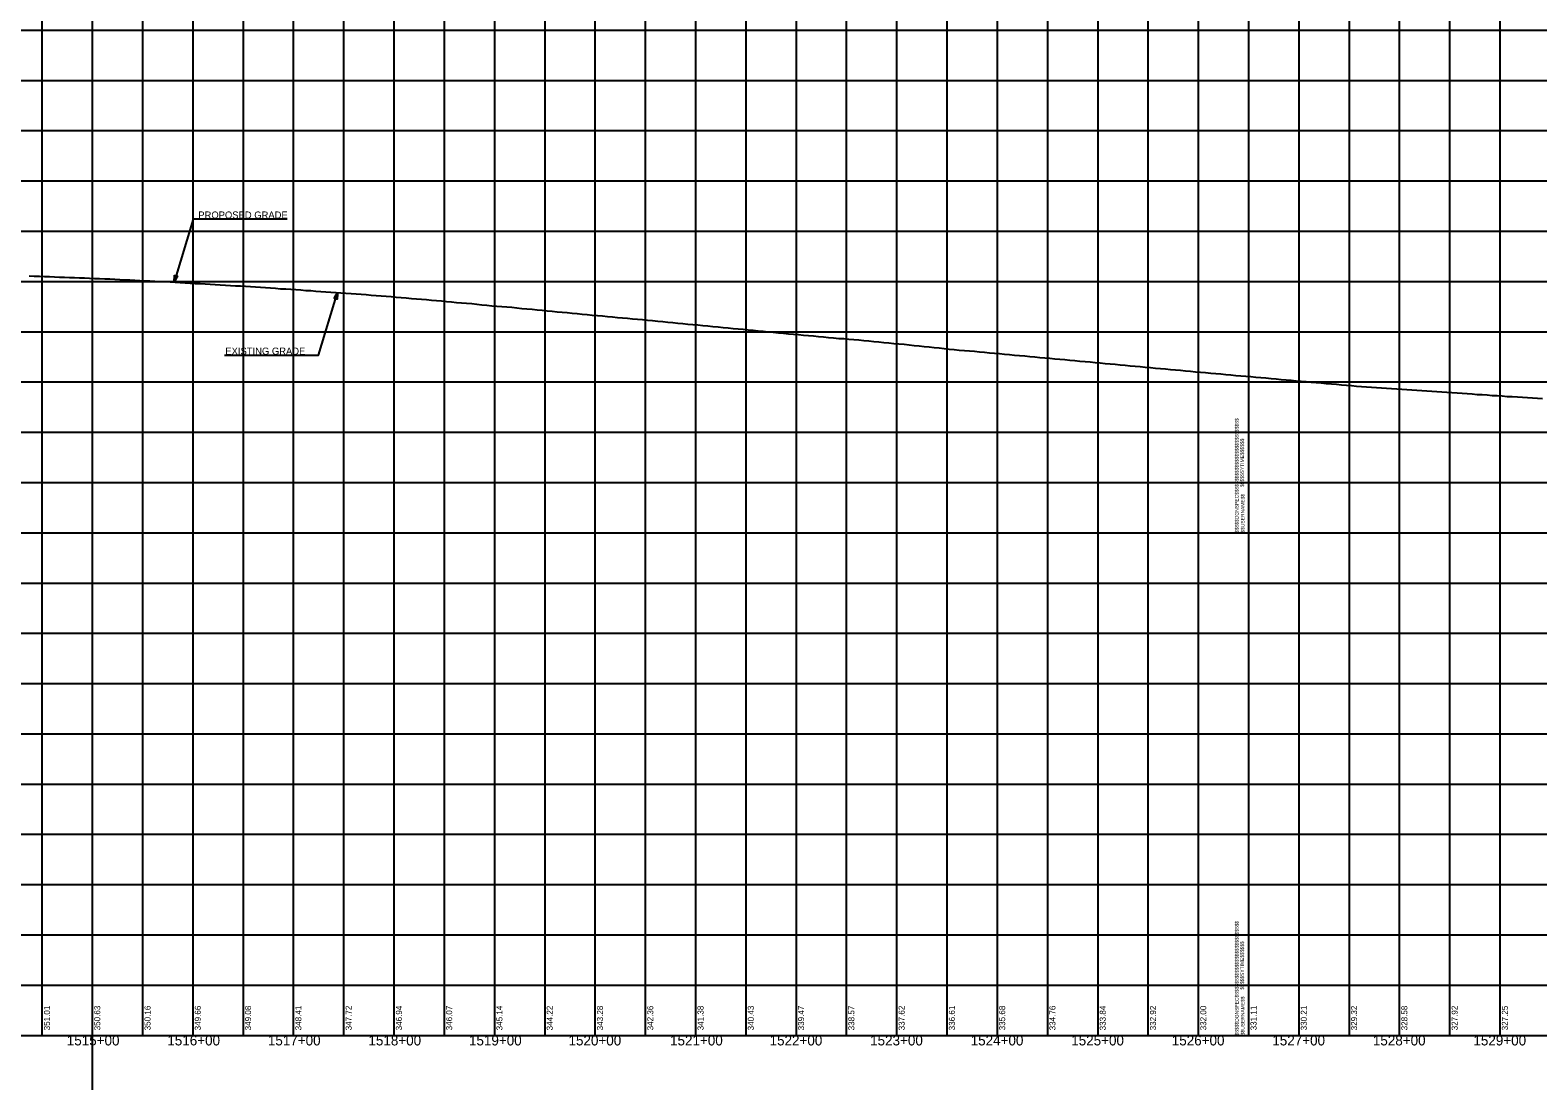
# Model space of a CAD drawing. Extents: x -90830 to 2015517, y -20856 to 836331.
# Drawn here: x 40362 to 41861, y -19432 to -18387 of the extents above; entities that cross this region are included whole.
import ezdxf

# ---------------------------------------------------------------- set-up
doc = ezdxf.new("R2010")
doc.units = 0
for name, color, linetype in [('Level 1', 7, 'Continuous'), ('RD_DDB_Profile_EX', 7, 'Continuous'), ('RD_DDB_StaTX', 7, 'Continuous'), ('RD_DDB_StripGrade', 7, 'Continuous'), ('RD_GPK_Profile_Cell', 7, 'Continuous'), ('RD_PD_Final_TX', 7, 'Continuous')]:
    doc.layers.add(name, color=color, linetype=linetype)

msp = doc.modelspace()

# ---------------------------------------------------------------- linework, layer by layer
at = {"layer": 'Level 1'}
for p, q in [((40423.5, -12693.4), (40423.5, -20856.1)), ((40373.5, -17886.5), (40373.5, -18386.5)), ((40423.5, -17886.5), (40423.5, -18386.5)), ((40473.5, -17886.5), (40473.5, -18386.5)), ((40523.5, -17886.5), (40523.5, -18386.5)), ((40573.5, -17886.5), (40573.5, -18386.5)), ((40623.5, -17886.5), (40623.5, -18386.5)), ((40673.5, -17886.5), (40673.5, -18386.5)), ((40723.5, -17886.5), (40723.5, -18386.5)), ((40773.5, -17886.5), (40773.5, -18386.5)), ((40823.5, -17886.5), (40823.5, -18386.5)), ((40873.5, -17886.5), (40873.5, -18386.5)), ((40923.5, -17886.5), (40923.5, -18386.5)), ((40973.5, -17886.5), (40973.5, -18386.5)), ((41023.5, -17886.5), (41023.5, -18386.5)), ((41073.5, -17886.5), (41073.5, -18386.5)), ((41123.5, -17886.5), (41123.5, -18386.5)), ((41173.5, -17886.5), (41173.5, -18386.5)), ((41223.5, -17886.5), (41223.5, -18386.5)), ((41273.5, -17886.5), (41273.5, -18386.5)), ((41323.5, -17886.5), (41323.5, -18386.5)), ((41373.5, -17886.5), (41373.5, -18386.5)), ((41423.5, -17886.5), (41423.5, -18386.5)), ((41473.5, -17886.5), (41473.5, -18386.5)), ((41523.5, -17886.5), (41523.5, -18386.5)), ((41573.5, -17886.5), (41573.5, -18386.5)), ((41573.5, -17886.5), (41573.5, -18386.5)), ((41573.5, -17886.5), (41573.5, -18386.5)), ((41623.5, -17886.5), (41623.5, -18386.5)), ((41673.5, -17886.5), (41673.5, -18386.5)), ((41723.5, -17886.5), (41723.5, -18386.5)), ((41773.5, -17886.5), (41773.5, -18386.5)), ((41823.5, -17886.5), (41823.5, -18386.5)), ((39973.5, -18386.5), (41573.5, -18386.5)), ((39973.5, -18386.5), (41573.5, -18386.5)), ((40373.5, -18386.5), (40373.5, -18886.5)), ((40423.5, -18386.5), (40423.5, -18886.5)), ((40473.5, -18386.5), (40473.5, -18886.5)), ((40523.5, -18386.5), (40523.5, -18886.5)), ((40573.5, -18386.5), (40573.5, -18886.5)), ((40623.5, -18386.5), (40623.5, -18886.5)), ((40673.5, -18386.5), (40673.5, -18886.5)), ((40723.5, -18386.5), (40723.5, -18886.5)), ((40773.5, -18386.5), (40773.5, -18886.5)), ((40823.5, -18386.5), (40823.5, -18886.5)), ((40873.5, -18386.5), (40873.5, -18886.5)), ((40923.5, -18386.5), (40923.5, -18886.5)), ((40973.5, -18386.5), (40973.5, -18886.5)), ((41023.5, -18386.5), (41023.5, -18886.5)), ((41073.5, -18386.5), (41073.5, -18886.5)), ((41123.5, -18386.5), (41123.5, -18886.5)), ((41173.5, -18386.5), (41173.5, -18886.5)), ((41223.5, -18386.5), (41223.5, -18886.5)), ((41273.5, -18386.5), (41273.5, -18886.5)), ((41323.5, -18386.5), (41323.5, -18886.5)), ((41373.5, -18386.5), (41373.5, -18886.5)), ((41423.5, -18386.5), (41423.5, -18886.5)), ((41473.5, -18386.5), (41473.5, -18886.5)), ((41523.5, -18386.5), (41523.5, -18886.5)), ((41573.5, -18386.5), (41573.5, -18886.5)), ((41573.5, -18386.5), (41573.5, -18886.5)), ((41573.5, -18386.5), (43173.5, -18386.5)), ((41573.5, -18386.5), (41573.5, -18886.5)), ((41573.5, -18386.5), (43173.5, -18386.5)), ((41623.5, -18386.5), (41623.5, -18886.5)), ((41673.5, -18386.5), (41673.5, -18886.5)), ((41723.5, -18386.5), (41723.5, -18886.5)), ((41773.5, -18386.5), (41773.5, -18886.5)), ((41823.5, -18386.5), (41823.5, -18886.5)), ((39973.5, -18436.5), (41573.5, -18436.5)), ((41573.5, -18436.5), (43173.5, -18436.5)), ((39973.5, -18486.5), (41573.5, -18486.5)), ((41573.5, -18486.5), (43173.5, -18486.5)), ((39973.5, -18536.5), (41573.5, -18536.5)), ((41573.5, -18536.5), (43173.5, -18536.5)), ((39973.5, -18586.5), (41573.5, -18586.5)), ((41573.5, -18586.5), (43173.5, -18586.5)), ((39973.5, -18636.5), (41573.5, -18636.5)), ((41573.5, -18636.5), (43173.5, -18636.5)), ((39973.5, -18686.5), (41573.5, -18686.5)), ((41573.5, -18686.5), (43173.5, -18686.5)), ((39973.5, -18736.5), (41573.5, -18736.5)), ((41573.5, -18736.5), (43173.5, -18736.5)), ((39973.5, -18786.5), (41573.5, -18786.5)), ((41573.5, -18786.5), (43173.5, -18786.5)), ((39973.5, -18836.5), (41573.5, -18836.5)), ((41573.5, -18836.5), (43173.5, -18836.5)), ((39973.5, -18886.5), (41573.5, -18886.5)), ((39973.5, -18886.5), (41573.5, -18886.5)), ((40373.5, -18886.5), (40373.5, -19386.5)), ((40423.5, -18886.5), (40423.5, -19386.5)), ((40473.5, -18886.5), (40473.5, -19386.5)), ((40523.5, -18886.5), (40523.5, -19386.5)), ((40573.5, -18886.5), (40573.5, -19386.5)), ((40623.5, -18886.5), (40623.5, -19386.5)), ((40673.5, -18886.5), (40673.5, -19386.5)), ((40723.5, -18886.5), (40723.5, -19386.5)), ((40773.5, -18886.5), (40773.5, -19386.5)), ((40823.5, -18886.5), (40823.5, -19386.5)), ((40873.5, -18886.5), (40873.5, -19386.5)), ((40923.5, -18886.5), (40923.5, -19386.5)), ((40973.5, -18886.5), (40973.5, -19386.5)), ((41023.5, -18886.5), (41023.5, -19386.5)), ((41073.5, -18886.5), (41073.5, -19386.5)), ((41123.5, -18886.5), (41123.5, -19386.5)), ((41173.5, -18886.5), (41173.5, -19386.5)), ((41223.5, -18886.5), (41223.5, -19386.5)), ((41273.5, -18886.5), (41273.5, -19386.5)), ((41323.5, -18886.5), (41323.5, -19386.5)), ((41373.5, -18886.5), (41373.5, -19386.5)), ((41423.5, -18886.5), (41423.5, -19386.5)), ((41473.5, -18886.5), (41473.5, -19386.5)), ((41523.5, -18886.5), (41523.5, -19386.5)), ((41573.5, -18886.5), (43173.5, -18886.5)), ((41573.5, -18886.5), (41573.5, -19386.5)), ((41573.5, -18886.5), (41573.5, -19386.5)), ((41573.5, -18886.5), (43173.5, -18886.5)), ((41573.5, -18886.5), (41573.5, -19386.5)), ((41623.5, -18886.5), (41623.5, -19386.5)), ((41673.5, -18886.5), (41673.5, -19386.5)), ((41723.5, -18886.5), (41723.5, -19386.5)), ((41773.5, -18886.5), (41773.5, -19386.5)), ((41823.5, -18886.5), (41823.5, -19386.5)), ((39973.5, -18936.5), (41573.5, -18936.5)), ((41573.5, -18936.5), (43173.5, -18936.5)), ((39973.5, -18986.5), (41573.5, -18986.5)), ((41573.5, -18986.5), (43173.5, -18986.5)), ((39973.5, -19036.5), (41573.5, -19036.5)), ((41573.5, -19036.5), (43173.5, -19036.5)), ((39973.5, -19086.5), (41573.5, -19086.5)), ((41573.5, -19086.5), (43173.5, -19086.5)), ((39973.5, -19136.5), (41573.5, -19136.5)), ((41573.5, -19136.5), (43173.5, -19136.5)), ((39973.5, -19186.5), (41573.5, -19186.5)), ((41573.5, -19186.5), (43173.5, -19186.5)), ((39973.5, -19236.5), (41573.5, -19236.5)), ((41573.5, -19236.5), (43173.5, -19236.5)), ((39973.5, -19286.5), (41573.5, -19286.5)), ((41573.5, -19286.5), (43173.5, -19286.5)), ((39973.5, -19336.5), (41573.5, -19336.5)), ((41573.5, -19336.5), (43173.5, -19336.5)), ((39973.5, -19386.5), (41573.5, -19386.5)), ((41573.5, -19386.5), (43173.5, -19386.5))]:
    msp.add_line(p, q, dxfattribs=at)
at = {"layer": 'RD_DDB_Profile_EX'}
for points in [[(40360.9, -18630.9), (40365.9, -18631.2), (40370.9, -18631.4), (40375.9, -18631.6), (40380.9, -18631.7), (40385.9, -18631.9), (40390.9, -18632.1), (40395.9, -18632.3), (40400.9, -18632.5), (40405.9, -18632.6), (40410.9, -18632.9), (40415.9, -18633), (40420.9, -18633.3)], [(40420.9, -18633.3), (40425.9, -18633.5), (40430.9, -18633.6), (40435.9, -18633.8), (40440.9, -18634), (40445.9, -18634.3), (40450.9, -18634.6), (40455.9, -18634.8), (40460.9, -18635), (40465.9, -18635.3), (40470.9, -18635.6), (40475.9, -18635.8), (40480.9, -18636), (40485.9, -18636.2), (40490.9, -18636.5), (40495.9, -18636.7), (40500.9, -18636.9), (40505.9, -18637.2), (40510.9, -18637.6), (40515.9, -18637.8), (40520.9, -18638.1), (40525.9, -18638.4), (40530.9, -18638.7), (40535.9, -18638.9), (40540.9, -18639.2), (40545.9, -18639.6), (40550.9, -18639.9), (40555.9, -18640.1), (40560.9, -18640.4), (40565.9, -18640.7), (40570.9, -18641), (40575.9, -18641.2), (40580.9, -18641.6), (40585.9, -18642), (40590.9, -18642.3), (40595.9, -18642.5), (40600.9, -18643), (40605.9, -18643.3), (40610.9, -18643.7), (40615.9, -18644), (40620.9, -18644.3), (40625.9, -18644.6), (40630.9, -18645), (40635.9, -18645.4), (40640.9, -18645.6), (40645.9, -18646), (40650.9, -18646.4), (40655.9, -18646.7), (40660.9, -18647), (40665.9, -18647.4), (40670.9, -18647.8), (40675.9, -18648.1), (40680.9, -18648.4), (40685.9, -18648.8), (40690.9, -18649.2), (40695.9, -18649.6), (40700.9, -18650), (40705.9, -18650.4), (40710.9, -18650.9), (40715.9, -18651.3), (40720.9, -18651.6), (40725.9, -18652.1), (40730.9, -18652.5), (40735.9, -18652.9), (40740.9, -18653.4), (40745.9, -18653.8), (40750.9, -18654.2), (40755.9, -18654.6), (40760.9, -18655), (40765.9, -18655.5), (40770.9, -18655.9), (40775.9, -18656.4), (40780.9, -18656.9), (40785.9, -18657.3), (40790.9, -18657.8), (40795.9, -18658.2), (40800.9, -18658.6), (40805.9, -18659.1), (40810.9, -18659.7), (40815.9, -18660.1), (40820.9, -18660.6), (40825.9, -18661), (40830.9, -18661.5), (40835.9, -18661.9), (40840.9, -18662.2), (40845.9, -18662.8), (40850.9, -18663.3), (40855.9, -18663.8), (40860.9, -18664.2), (40865.9, -18664.7), (40870.9, -18665.2), (40875.9, -18665.6), (40880.9, -18666.1), (40885.9, -18666.6), (40890.9, -18667), (40895.9, -18667.5), (40900.9, -18668), (40905.9, -18668.4), (40910.9, -18668.9), (40915.9, -18669.4), (40920.9, -18669.9)], [(40920.9, -18669.9), (40925.9, -18670.4), (40930.9, -18670.8), (40935.9, -18671.3), (40940.9, -18671.8), (40945.9, -18672.2), (40950.9, -18672.6), (40955.9, -18673.1), (40960.9, -18673.6), (40965.9, -18674), (40970.9, -18674.5), (40975.9, -18674.9), (40980.9, -18675.4), (40985.9, -18675.9), (40990.9, -18676.3), (40995.9, -18676.9), (41000.9, -18677.4), (41005.9, -18678), (41010.9, -18678.4), (41015.9, -18678.9), (41020.9, -18679.4), (41025.9, -18679.8), (41030.9, -18680.3), (41035.9, -18680.7), (41040.9, -18681.3), (41045.9, -18681.7), (41050.9, -18682.2), (41055.9, -18682.7), (41060.9, -18683.2), (41065.9, -18683.7), (41070.9, -18684.1), (41075.9, -18684.6), (41080.9, -18685.1), (41085.9, -18685.6), (41090.9, -18686.1), (41095.9, -18686.5), (41100.9, -18687), (41105.9, -18687.5), (41110.9, -18687.9), (41115.9, -18688.5), (41120.9, -18688.9), (41125.9, -18689.3), (41130.9, -18689.8), (41135.9, -18690.2), (41140.9, -18690.7), (41145.9, -18691.1), (41150.9, -18691.6), (41155.9, -18692.1), (41160.9, -18692.5), (41165.9, -18693.1), (41170.9, -18693.4), (41175.9, -18693.9), (41180.9, -18694.4), (41185.9, -18694.7), (41190.9, -18695.2), (41195.9, -18695.7), (41200.9, -18696.1), (41205.9, -18696.7), (41210.9, -18697.1), (41215.9, -18697.6), (41220.9, -18698.1), (41225.9, -18698.6), (41230.9, -18699), (41235.9, -18699.5), (41240.9, -18700.1), (41245.9, -18700.6), (41250.9, -18701.1), (41255.9, -18701.6), (41260.9, -18702.1), (41265.9, -18702.7), (41270.9, -18703.2), (41275.9, -18703.7), (41280.9, -18704.2), (41285.9, -18704.7), (41290.9, -18705.1), (41295.9, -18705.6), (41300.9, -18706), (41305.9, -18706.5), (41310.9, -18707), (41315.9, -18707.4), (41320.9, -18707.9), (41325.9, -18708.3), (41330.9, -18708.8), (41335.9, -18709.3), (41340.9, -18709.7), (41345.9, -18710.2), (41350.9, -18710.6), (41355.9, -18711.1), (41360.9, -18711.6), (41365.9, -18712), (41370.9, -18712.5), (41375.9, -18712.9), (41380.9, -18713.4), (41385.9, -18713.9), (41390.9, -18714.3), (41395.9, -18714.8), (41400.9, -18715.2), (41405.9, -18715.7), (41410.9, -18716.2), (41415.9, -18716.6), (41420.9, -18717.1)], [(41420.9, -18717.1), (41425.9, -18717.5), (41430.9, -18718), (41435.9, -18718.5), (41440.9, -18718.9), (41445.9, -18719.4), (41450.9, -18719.8), (41455.9, -18720.3), (41460.9, -18720.8), (41465.9, -18721.2), (41470.9, -18721.7), (41475.9, -18722.2), (41480.9, -18722.6), (41485.9, -18723.1), (41490.9, -18723.5), (41495.9, -18724), (41500.9, -18724.5), (41505.9, -18724.9), (41510.9, -18725.4), (41515.9, -18725.8), (41520.9, -18726.3), (41525.9, -18726.7), (41530.9, -18727.2), (41535.9, -18727.6), (41540.9, -18728.1), (41545.9, -18728.5), (41550.9, -18729), (41555.9, -18729.4), (41560.9, -18729.9), (41565.9, -18730.3), (41570.9, -18730.8), (41575.9, -18731.2), (41580.9, -18731.6), (41585.9, -18732.1), (41590.9, -18732.5), (41595.9, -18733), (41600.9, -18733.4), (41605.9, -18733.9), (41610.9, -18734.3), (41615.9, -18734.8), (41620.9, -18735.2), (41625.9, -18735.7), (41630.9, -18736.1), (41635.9, -18736.6), (41640.9, -18737), (41645.9, -18737.5), (41650.9, -18737.9), (41655.9, -18738.3), (41660.9, -18738.8), (41665.9, -18739.2), (41670.9, -18739.7), (41675.9, -18740.1), (41680.9, -18740.6), (41685.9, -18741), (41690.9, -18741.4), (41695.9, -18741.8), (41700.9, -18742.1), (41705.9, -18742.4), (41710.9, -18742.8), (41715.9, -18743.1), (41720.9, -18743.4), (41725.9, -18743.8), (41730.9, -18744.1), (41735.9, -18744.4), (41740.9, -18744.8), (41745.9, -18745.1), (41750.9, -18745.4), (41755.9, -18745.8), (41760.9, -18746.1), (41765.9, -18746.4), (41770.9, -18746.8), (41775.9, -18747.1), (41780.9, -18747.4), (41785.9, -18747.8), (41790.9, -18748.1), (41795.9, -18748.4), (41800.9, -18748.8), (41805.9, -18749.1), (41810.9, -18749.4), (41815.9, -18749.8), (41820.9, -18750.1), (41825.9, -18750.4), (41830.9, -18750.8), (41835.9, -18751.1), (41840.9, -18751.4), (41845.9, -18751.7), (41850.9, -18752.1), (41855.9, -18752.4), (41860.9, -18752.7), (41865.9, -18753.1)]]:
    msp.add_lwpolyline(points, dxfattribs=at)
at = {"layer": 'RD_GPK_Profile_Cell'}
msp.add_line((4823.5, -19386.5), (75223.5, -19386.5), dxfattribs=at)
at = {"layer": 'RD_PD_Final_TX'}
for p, q in [((40505, -18637.1), (40505.3, -18630.4)), ((40506.9, -18630.9), (40505, -18637.1)), ((40505, -18637.1), (40508.4, -18631.4)), ((40505.3, -18630.4), (40508.4, -18631.4)), ((40667.5, -18647.5), (40664, -18653.2)), ((40667.1, -18654.2), (40664, -18653.2)), ((40665.6, -18653.7), (40667.5, -18647.5)), ((40667.5, -18647.5), (40667.1, -18654.2))]:
    msp.add_line(p, q, dxfattribs=at)
for points in [[(40617.4, -18574.7), (40524, -18574.7), (40505, -18637.1)], [(40506.8, -18631), (40505.1, -18636.7), (40506.8, -18630.9), (40505.1, -18636.5), (40506.7, -18630.9), (40505.1, -18636.3), (40506.6, -18630.9), (40505.1, -18636), (40506.6, -18630.9), (40505.1, -18635.7), (40506.5, -18630.8), (40505.1, -18635.3), (40506.4, -18630.8), (40505.2, -18635), (40506.3, -18630.8), (40505.2, -18634.7), (40506.3, -18630.8), (40505.2, -18634.4), (40506.2, -18630.8), (40505.2, -18634.1), (40506.1, -18630.8), (40505.2, -18633.8), (40506.1, -18630.7), (40505.3, -18633.3), (40506, -18630.7), (40505.2, -18633), (40505.9, -18630.7), (40505.3, -18632.6), (40505.8, -18630.7), (40505.3, -18632.2), (40505.7, -18630.6), (40505.3, -18631.9), (40505.7, -18630.6), (40505.3, -18631.6), (40505.6, -18630.5), (40505.4, -18631.2), (40505.5, -18630.6), (40505.4, -18630.8), (40505.4, -18630.6)], [(40505.2, -18636.7), (40506.9, -18631), (40505.3, -18636.5), (40507, -18631), (40505.4, -18636.3), (40507, -18631), (40505.5, -18636.2), (40507.1, -18631), (40505.6, -18636), (40507.2, -18631), (40505.7, -18635.8), (40507.2, -18631.1), (40505.9, -18635.6), (40507.3, -18631.1), (40506, -18635.3), (40507.4, -18631.1), (40506.1, -18635.1), (40507.4, -18631.1), (40506.3, -18634.8), (40507.5, -18631.1), (40506.4, -18634.6), (40507.5, -18631.2), (40506.6, -18634.3), (40507.6, -18631.2), (40506.8, -18634), (40507.7, -18631.2), (40507, -18633.7), (40507.7, -18631.2), (40507.1, -18633.5), (40507.8, -18631.2), (40507.3, -18633.1), (40507.8, -18631.3), (40507.4, -18632.9), (40507.9, -18631.3), (40507.6, -18632.7), (40508, -18631.3), (40507.8, -18632.3), (40508.1, -18631.3), (40507.9, -18632.1), (40508.2, -18631.4), (40508, -18632), (40508.3, -18631.5), (40508.3, -18631.4), (40508.2, -18631.4)], [(40555, -18709.9), (40648.4, -18709.9), (40667.5, -18647.5)], [(40667.3, -18647.9), (40665.6, -18653.6), (40667.2, -18648.1), (40665.5, -18653.6), (40667.1, -18648.3), (40665.4, -18653.6), (40667, -18648.4), (40665.4, -18653.6), (40666.9, -18648.6), (40665.3, -18653.6), (40666.8, -18648.8), (40665.3, -18653.6), (40666.6, -18649), (40665.2, -18653.5), (40666.5, -18649.3), (40665.1, -18653.5), (40666.3, -18649.6), (40665.1, -18653.5), (40666.2, -18649.8), (40665, -18653.5), (40666, -18650), (40664.9, -18653.5), (40665.9, -18650.3), (40664.9, -18653.4), (40665.7, -18650.7), (40664.8, -18653.4), (40665.5, -18650.9), (40664.8, -18653.4), (40665.3, -18651.2), (40664.7, -18653.4), (40665.2, -18651.5), (40664.6, -18653.3), (40665, -18651.7), (40664.6, -18653.3), (40664.9, -18651.9), (40664.5, -18653.3), (40664.7, -18652.3), (40664.4, -18653.3), (40664.6, -18652.5), (40664.3, -18653.3), (40664.5, -18652.6), (40664.2, -18653.2), (40664.1, -18653.2), (40664.2, -18653.2)], [(40665.7, -18653.6), (40667.4, -18647.9), (40665.7, -18653.7), (40667.4, -18648.2), (40665.8, -18653.7), (40667.4, -18648.4), (40665.8, -18653.7), (40667.4, -18648.6), (40665.9, -18653.7), (40667.4, -18649), (40666, -18653.8), (40667.3, -18649.3), (40666.1, -18653.8), (40667.3, -18649.6), (40666.1, -18653.8), (40667.3, -18650), (40666.2, -18653.8), (40667.3, -18650.2), (40666.3, -18653.9), (40667.3, -18650.5), (40666.4, -18653.9), (40667.3, -18650.9), (40666.4, -18653.9), (40667.2, -18651.3), (40666.5, -18653.9), (40667.2, -18651.6), (40666.6, -18654), (40667.2, -18652), (40666.7, -18654), (40667.2, -18652.4), (40666.7, -18654), (40667.1, -18652.7), (40666.8, -18654), (40667.1, -18653), (40666.9, -18654.1), (40667.1, -18653.4), (40667, -18654), (40667.1, -18653.8), (40667, -18654)]]:
    msp.add_lwpolyline(points, dxfattribs=at)

# ---------------------------------------------------------------- texts
at = {"layer": 'Level 1'}
for s, p in [('$$$$$DGNSPEC$$$$$$$$$$$$$$$$$$$$$$$$$$$$', (41563.6, -18886.6)), ('$$$$$SYTIME$$$$$$', (41568.9, -18841)), ('$$USERNAME$$', (41569.5, -18886.4)), ('$$$$$DGNSPEC$$$$$$$$$$$$$$$$$$$$$$$$$$$$', (41563.6, -19386.6)), ('$$$$$SYTIME$$$$$$', (41568.9, -19341)), ('$$USERNAME$$', (41569.5, -19386.4))]:
    msp.add_text(s, height=3.544, rotation=90, dxfattribs=at).set_placement(p)
at = {"layer": 'RD_DDB_StaTX'}
for s, p in [('1515+00', (40398.2, -19396.5)), ('1516+00', (40498.2, -19396.5)), ('1517+00', (40598.2, -19396.5)), ('1518+00', (40698.2, -19396.5)), ('1519+00', (40798.2, -19396.5)), ('1520+00', (40897.2, -19396.5)), ('1521+00', (40998.2, -19396.5)), ('1522+00', (41097.2, -19396.5)), ('1523+00', (41197.2, -19396.5)), ('1524+00', (41297.2, -19396.5)), ('1525+00', (41397.2, -19396.5)), ('1526+00', (41497.2, -19396.5)), ('1527+00', (41597.2, -19396.5)), ('1528+00', (41697.2, -19396.5)), ('1529+00', (41797.2, -19396.5))]:
    msp.add_text(s, height=10, dxfattribs=at).set_placement(p)
at = {"layer": 'RD_DDB_StripGrade'}
for s, p in [('351.01', (40381.5, -19381.5)), ('350.63', (40431.5, -19381.5)), ('350.16', (40481.5, -19381.5)), ('349.66', (40531.5, -19381.5)), ('349.08', (40581.5, -19381.5)), ('348.41', (40631.5, -19381.5)), ('347.72', (40681.5, -19381.5)), ('346.94', (40731.5, -19381.5)), ('346.07', (40781.5, -19381.5)), ('345.14', (40831.5, -19381.5)), ('344.22', (40881.5, -19381.5)), ('343.28', (40931.5, -19381.5)), ('342.36', (40981.5, -19381.5)), ('341.38', (41031.5, -19381.5)), ('340.43', (41081.5, -19381.5)), ('339.47', (41131.5, -19381.5)), ('338.57', (41181.5, -19381.5)), ('337.62', (41231.5, -19381.5)), ('336.61', (41281.5, -19381.5)), ('335.68', (41331.5, -19381.5)), ('334.76', (41381.5, -19381.5)), ('333.84', (41431.5, -19381.5)), ('332.92', (41481.5, -19381.5)), ('332.00', (41531.5, -19381.5)), ('331.11', (41581.5, -19381.5)), ('330.21', (41631.5, -19381.5)), ('329.32', (41681.5, -19381.5)), ('328.58', (41731.5, -19381.5)), ('327.92', (41781.5, -19381.5)), ('327.25', (41831.5, -19381.5))]:
    msp.add_text(s, height=6, rotation=90, dxfattribs=at).set_placement(p)
at = {"layer": 'RD_PD_Final_TX'}
for s, p in [('PROPOSED GRADE', (40529, -18573.9)), ('EXISTING GRADE', (40555.9, -18709.3))]:
    msp.add_text(s, height=7, dxfattribs=at).set_placement(p)

doc.saveas('drawing.dxf')
